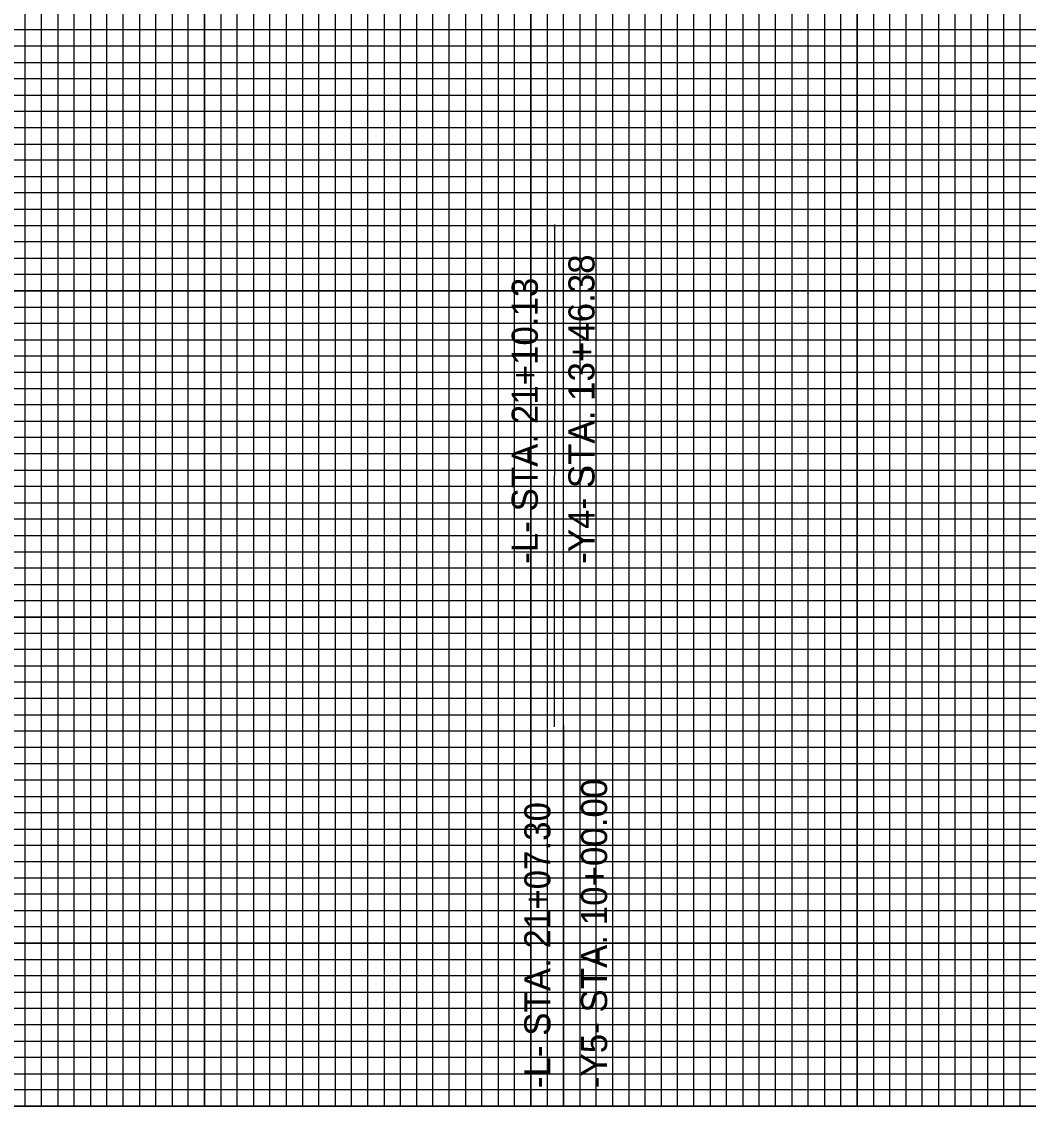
# Model space of a CAD drawing. Extents: x 1623313 to 1628771, y 891211 to 901910.
# Drawn here: x 1624473.9 to 1624782.4, y 901334.4 to 901666.9 of the extents above; entities that cross this region are included whole.
import ezdxf

# ---------------------------------------------------------------- set-up
doc = ezdxf.new("R2010")
doc.units = 0
for name, color, linetype in [('Prop DSN Text', 7, 'Continuous'), ('Scratch_Level_0', 7, 'Continuous'), ('Sheet DOT Grid CELL', 7, 'Continuous'), ('Sheet Layout Profile Border Port 1', 7, 'Continuous'), ('Sheet Profile CELL', 7, 'Continuous'), ('Sheet Profile Grid Major CELL', 7, 'Continuous'), ('Sheet Profile Grid Middle CELL', 7, 'Continuous'), ('Sheet Profile Grid Minor CELL', 7, 'Continuous')]:
    doc.layers.add(name, color=color, linetype=linetype)

msp = doc.modelspace()

# ---------------------------------------------------------------- linework, layer by layer
at = {"layer": 'Prop DSN Text'}
for q in [(1624639.95, 901334.45), (1624639.98, 901451.14)]:
    msp.add_line((1624639.98, 901451.14), q, dxfattribs=at)
msp.add_lwpolyline([(1624637.18, 901450.82), (1624637.19, 901450.83), (1624637.32, 901604.79)], dxfattribs=at)
at = {"layer": 'Scratch_Level_0'}
msp.add_lwpolyline([(1623529.95, 901824.45), (1624929.95, 901824.45), (1624929.95, 901334.45), (1623529.95, 901334.45)], close=True, dxfattribs=at)
at = {"layer": 'Sheet DOT Grid CELL'}
for p, q in [((1624479.95, 901334.45), (1624479.95, 901834.45)), ((1624529.95, 901334.45), (1624529.95, 901834.45)), ((1624579.95, 901334.45), (1624579.95, 901834.45)), ((1624629.95, 901334.45), (1624629.95, 901834.45)), ((1624679.95, 901334.45), (1624679.95, 901834.45)), ((1624729.95, 901334.45), (1624729.95, 901834.45)), ((1624779.95, 901334.45), (1624779.95, 901696.9)), ((1624979.95, 901634.45), (1623479.95, 901634.45)), ((1624979.95, 901584.45), (1623479.95, 901584.45)), ((1624979.95, 901534.45), (1623479.95, 901534.45)), ((1624979.95, 901484.45), (1623479.95, 901484.45)), ((1624979.95, 901434.45), (1623479.95, 901434.45)), ((1624979.95, 901384.45), (1623479.95, 901384.45))]:
    msp.add_line(p, q, dxfattribs=at)
at = {"layer": 'Sheet Layout Profile Border Port 1'}
msp.add_lwpolyline([(1623529.95, 901673.4), (1623529.95, 901334.45), (1624929.95, 901334.45), (1624929.95, 901673.4)], dxfattribs=at)
at = {"layer": 'Sheet Profile CELL'}
msp.add_line((1623479.95, 901334.45), (1624979.95, 901334.45), dxfattribs=at)
at = {"layer": 'Sheet Profile Grid Major CELL'}
for points in [[(1624429.95, 901334.45), (1624479.95, 901334.45), (1624479.95, 901834.45), (1624529.95, 901834.45), (1624529.95, 901334.45), (1624579.95, 901334.45), (1624579.95, 901834.45), (1624629.95, 901834.45), (1624629.95, 901334.45), (1624679.95, 901334.45), (1624679.95, 901834.45), (1624729.95, 901834.45), (1624729.95, 901334.45), (1624779.95, 901334.45), (1624779.95, 901834.45), (1624806.25, 901834.45)], [(1624979.95, 901634.45), (1623479.95, 901634.45), (1623479.95, 901584.45), (1624979.95, 901584.45)], [(1624979.95, 901534.45), (1623479.95, 901534.45), (1623479.95, 901484.45), (1624979.95, 901484.45)], [(1624979.95, 901434.45), (1623479.95, 901434.45), (1623479.95, 901434.45), (1623479.95, 901384.45), (1624979.95, 901384.45)]]:
    msp.add_lwpolyline(points, dxfattribs=at)
at = {"layer": 'Sheet Profile Grid Middle CELL'}
for points in [[(1624454.95, 901334.45), (1624504.95, 901334.45), (1624504.95, 901834.45), (1624554.95, 901834.45), (1624554.95, 901334.45), (1624604.95, 901334.45), (1624604.95, 901834.45), (1624654.95, 901834.45), (1624654.95, 901334.45), (1624704.95, 901334.45), (1624704.95, 901834.45), (1624754.95, 901834.45), (1624754.95, 901334.45), (1624804.95, 901334.45)], [(1624979.95, 901659.45), (1623479.95, 901659.45), (1623479.95, 901609.45), (1624804.95, 901609.45)], [(1624979.95, 901559.45), (1623479.95, 901559.45), (1623479.95, 901509.45), (1624979.95, 901509.45)], [(1624979.95, 901459.45), (1623479.95, 901459.45), (1623479.95, 901409.45), (1624979.95, 901409.45)], [(1624979.95, 901359.45), (1623479.95, 901359.45)]]:
    msp.add_lwpolyline(points, dxfattribs=at)
at = {"layer": 'Sheet Profile Grid Minor CELL'}
for p, q in [((1624929.95, 901649.45), (1623529.95, 901649.45)), ((1623529.95, 901644.45), (1624929.95, 901644.45)), ((1624929.95, 901624.45), (1623529.95, 901624.45)), ((1623529.95, 901619.45), (1624929.95, 901619.45)), ((1624929.95, 901599.45), (1623529.95, 901599.45)), ((1623529.95, 901594.45), (1624929.95, 901594.45)), ((1624929.95, 901589.45), (1623529.95, 901589.45)), ((1623529.95, 901579.45), (1624929.95, 901579.45)), ((1624929.95, 901574.45), (1623529.95, 901574.45)), ((1623529.95, 901569.45), (1624929.95, 901569.45)), ((1624929.95, 901564.45), (1623529.95, 901564.45)), ((1623529.95, 901554.45), (1624929.95, 901554.45)), ((1624929.95, 901549.45), (1623529.95, 901549.45)), ((1623529.95, 901544.45), (1624929.95, 901544.45)), ((1624929.95, 901539.45), (1623529.95, 901539.45)), ((1623529.95, 901529.45), (1624929.95, 901529.45)), ((1624929.95, 901524.45), (1623529.95, 901524.45)), ((1623529.95, 901519.45), (1624929.95, 901519.45)), ((1624929.95, 901514.45), (1623529.95, 901514.45)), ((1623529.95, 901504.45), (1624929.95, 901504.45)), ((1624929.95, 901499.45), (1623529.95, 901499.45)), ((1623529.95, 901494.45), (1624929.95, 901494.45)), ((1624929.95, 901489.45), (1623529.95, 901489.45)), ((1623529.95, 901479.45), (1624929.95, 901479.45)), ((1624929.95, 901474.45), (1623529.95, 901474.45)), ((1623529.95, 901469.45), (1624929.95, 901469.45)), ((1624929.95, 901464.45), (1623529.95, 901464.45)), ((1623529.95, 901454.45), (1624929.95, 901454.45)), ((1624929.95, 901449.45), (1623529.95, 901449.45)), ((1624929.95, 901444.45), (1623529.95, 901444.45)), ((1624929.95, 901439.45), (1623529.95, 901439.45)), ((1623529.95, 901429.45), (1624929.95, 901429.45)), ((1624929.95, 901424.45), (1623529.95, 901424.45)), ((1623529.95, 901419.45), (1624929.95, 901419.45)), ((1624929.95, 901414.45), (1623529.95, 901414.45)), ((1623529.95, 901404.45), (1624929.95, 901404.45)), ((1624929.95, 901399.45), (1623529.95, 901399.45)), ((1623529.95, 901394.45), (1624929.95, 901394.45)), ((1624929.95, 901389.45), (1623529.95, 901389.45)), ((1623529.95, 901379.45), (1624929.95, 901379.45)), ((1624929.95, 901374.45), (1623529.95, 901374.45)), ((1623529.95, 901369.45), (1624929.95, 901369.45)), ((1624929.95, 901364.45), (1623529.95, 901364.45)), ((1623529.95, 901354.45), (1624929.95, 901354.45)), ((1624929.95, 901349.45), (1623529.95, 901349.45)), ((1623529.95, 901344.45), (1624929.95, 901344.45))]:
    msp.add_line(p, q, dxfattribs=at)
for points in [[(1624469.95, 901334.45), (1624474.95, 901334.45), (1624474.95, 901834.45)], [(1624484.95, 901834.45), (1624484.95, 901334.45), (1624489.95, 901334.45), (1624489.95, 901834.45)], [(1624494.95, 901834.45), (1624494.95, 901334.45), (1624499.95, 901334.45), (1624499.95, 901834.45)], [(1624509.95, 901834.45), (1624509.95, 901334.45), (1624514.95, 901334.45), (1624514.95, 901834.45)], [(1624519.95, 901834.45), (1624519.95, 901334.45), (1624524.95, 901334.45), (1624524.95, 901834.45)], [(1624534.95, 901834.45), (1624534.95, 901334.45), (1624539.95, 901334.45), (1624539.95, 901834.45)], [(1624544.95, 901834.45), (1624544.95, 901334.45), (1624549.95, 901334.45), (1624549.95, 901834.45)], [(1624559.95, 901834.45), (1624559.95, 901334.45), (1624564.95, 901334.45), (1624564.95, 901834.45)], [(1624569.95, 901834.45), (1624569.95, 901334.45), (1624574.95, 901334.45), (1624574.95, 901834.45)], [(1624584.95, 901834.45), (1624584.95, 901334.45), (1624589.95, 901334.45), (1624589.95, 901834.45)], [(1624594.95, 901834.45), (1624594.95, 901334.45), (1624599.95, 901334.45), (1624599.95, 901834.45)], [(1624609.95, 901834.45), (1624609.95, 901334.45), (1624614.95, 901334.45), (1624614.95, 901834.45)], [(1624619.95, 901834.45), (1624619.95, 901334.45), (1624624.95, 901334.45), (1624624.95, 901834.45)], [(1624634.95, 901834.45), (1624634.95, 901334.45), (1624639.95, 901334.45), (1624639.95, 901834.45)], [(1624644.95, 901834.45), (1624644.95, 901334.45), (1624649.95, 901334.45), (1624649.95, 901834.45)], [(1624659.95, 901834.45), (1624659.95, 901334.45), (1624664.95, 901334.45), (1624664.95, 901834.45)], [(1624669.95, 901834.45), (1624669.95, 901334.45)], [(1624669.95, 901334.45), (1624674.95, 901334.45), (1624674.95, 901834.45)], [(1624684.95, 901834.45), (1624684.95, 901334.45), (1624689.95, 901334.45), (1624689.95, 901834.45)], [(1624694.95, 901834.45), (1624694.95, 901334.45), (1624699.95, 901334.45), (1624699.95, 901834.45)], [(1624709.95, 901834.45), (1624709.95, 901334.45), (1624714.95, 901334.45), (1624714.95, 901834.45)], [(1624719.95, 901834.45), (1624719.95, 901334.45), (1624724.95, 901334.45), (1624724.95, 901834.45)], [(1624734.95, 901834.45), (1624734.95, 901334.45), (1624739.95, 901334.45), (1624739.95, 901834.45)], [(1624744.95, 901834.45), (1624744.95, 901334.45), (1624749.95, 901334.45), (1624749.95, 901834.45)], [(1624759.95, 901834.45), (1624759.95, 901334.45), (1624764.95, 901334.45), (1624764.95, 901834.45)], [(1624769.95, 901834.45), (1624769.95, 901334.45), (1624774.95, 901334.45), (1624774.95, 901834.45)], [(1624929.95, 901664.45), (1623529.95, 901664.45), (1623529.95, 901654.45), (1624929.95, 901654.45)], [(1624929.95, 901639.45), (1623529.95, 901639.45), (1623529.95, 901629.45), (1624929.95, 901629.45)], [(1624929.95, 901614.45), (1623529.95, 901614.45), (1623529.95, 901604.45), (1624929.95, 901604.45)], [(1624929.95, 901339.45), (1623529.95, 901339.45)]]:
    msp.add_lwpolyline(points, dxfattribs=at)

# ---------------------------------------------------------------- texts
at = {"layer": 'Prop DSN Text'}
for s, p in [('-Y4- STA. 13+46.38', (1624649.47, 901500.76)), ('-L- STA. 21+10.13', (1624632.09, 901500.76)), ('-Y5- STA. 10+00.00', (1624653.34, 901340.01)), ('-L- STA. 21+07.30', (1624635.96, 901340.01))]:
    msp.add_text(s, height=8, rotation=90, dxfattribs=at).set_placement(p)

doc.saveas('drawing.dxf')
